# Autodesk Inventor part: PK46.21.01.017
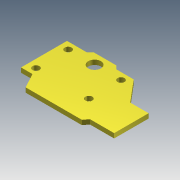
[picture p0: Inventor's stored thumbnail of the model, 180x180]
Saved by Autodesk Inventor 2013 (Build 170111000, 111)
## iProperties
Created: 2005-04
Part Number: PK46.21.01.017
Material: Steel, Mild
Document SubType Name: Modeling
Designer: salex
Manufacturer: Standard
Standards Organization: Custom
Density: 7.86 g/cm^3
Author: salex
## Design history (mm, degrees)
sketch "Эскиз1"
  geometry: L1 (0, 0)-(85, 0); L2 (85, 0)-(100, 15); L3 (100, 15)-(200, 15); L4 (200, 15)-(215, 0); L5 (215, 0)-(290, 0); L6 (290, 0)-(370, -95); L7 (370, -95)-(450, -95); L8 (450, -95)-(450, -245); L9 (450, -245)-(345, -245); L10 (345, -245)-(330, -265); L11 (330, -265)-(85, -265); L12 (85, -265)-(50, -200); L13 (50, -200)-(0, -200); L14 (0, -200)-(0, 0); C1 r 15 at (35, -30); C2 r 15 at (35, -170); C3 r 15 at (265, -30); C4 r 15 at (265, -170); C5 r 27.5 at (150, -30)
  constraints: 28 end point, 6 parallel, 5 centre point, 3 equal radius, 2 collinear, 1 horizontal, 1 perpendicular, 1 other
  dimensions: "d0" = 30 diameter of C1; "d2" = 140 distance of C2.centre C1.centre; "d3" = 0 horizontal distance of C2.centre C1.centre; "d4" = 0 vertical distance of C4.centre C2.centre; "d5" = 0 vertical distance of C3.centre C1.centre; "d6" = 0 horizontal distance of C4.centre C3.centre; "d7" = 230 distance of C3.centre C1.centre; "d8" = 115 distance of C5.centre C1.centre (= 0.5 x d7); "d9" = 0 vertical distance of C1.centre C5.centre; "d10" = 55 diameter of C5; "d11" = 35 distance from line of C1.centre L14; "d12" = 30 distance from line of C2.centre L13; "d13" = 200 distance between parallel lines of L1 L13; "d14" = 65 distance between parallel lines of L11 L13; "d15" = 280 distance between parallel lines of L11 L3; "d16" = 15 horizontal distance of L1.end L2.end; "d17" = 100 distance from line of L2.end L14; "d18" = 100 distance of L2.end L3.end; "d19" = 15 horizontal distance of L3.end L4.end; "d20" = 35 horizontal distance of L11.end L12.end; "d21" = 85 distance from line of L11.end L14; "d22" = 80 distance of L6.end L7.end; "d23" = 150 distance of L7.end L8.end; "d24" = 20 vertical distance of L9.end L10.end; "d25" = 15 horizontal distance of L9.end L10.end; "d26" = 160 distance from line of L8 L5.end; "d27" = 450 distance between parallel lines of L8 L14; "d28" = 245 distance of L10.end L11.end
extrude "Выдавливание1" new body sketch "Эскиз1" distance "d29" = 20; taper "d30" = 0 deg
body "Solid1"
